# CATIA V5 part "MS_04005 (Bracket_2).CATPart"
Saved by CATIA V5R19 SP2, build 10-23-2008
Part number: MS_04005
Bounding box of the stored display mesh (mm): x -11.248 to 11.248, y 76.359 to 104.129, z 0 to 1.5
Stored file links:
  C:\Users\33645\Documents\02-Etudes\2019-ECL\Trans Semestres\01-EPSA\03-Trans Saisons\Git\ELIZ-2021\MS_Miscellaneous_Finish_Assembly\MS_A0400 (Firewall)\Chappes\FR_04004.2 (Chape 2).CATPart
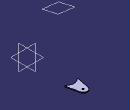
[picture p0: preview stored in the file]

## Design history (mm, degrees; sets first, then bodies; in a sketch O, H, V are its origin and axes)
SheetMetalParameters1: Thickness 1.5, BendRadius 4, KFactor 0.43175 {= log(min(100,max(20*SheetMetalParameters1.BendRadius,SheetMetalParameters1.Thickness)/SheetMetalParameters1.Thickness))/log(100)/2}, ReliefRadialLength 1, ReliefAxialLength 2, MinimumBendRadius 0
Body1 (main body)
  Sketch1 on xy-plane, origin (0, 0, 0), H (1, 0, 0), V (0, 1, 0)
    point P1 (-11.6743, 74.8566)
    line L1 (-11.2483, 76.9505) -> (-6.8595, 98.5247)
    point P2 (-6.8595, 98.5247)
    arc A1 centre (0, 97.1293) radius 7 from (-6.8595, 98.5247) to (0, 104.1293) cw
    point P4 (0, 104.1293)
    point P5 (0, 104.1293)
    point P6 (6.8595, 98.5247)
    point P7 (0, 97.1293)
    arc A2 centre (0, 97.1293) radius 7 from (6.8595, 98.5247) to (0, 104.1293) ccw
    point P8 (11.6743, 74.8566)
    line L2 (11.2483, 76.9505) -> (6.8595, 98.5247)
    circle A3 centre (0, 97.1293) radius 1.7
    arc A4 centre (0, 67.1293) radius 14 from (10.3874, 76.5156) to (-10.3874, 76.5156) ccw
    point P9 (0, 67.1293)
    arc A5 centre (10.7584, 76.8508) radius 0.5 from (10.3874, 76.5156) to (11.2483, 76.9505) ccw
    point P12 (10.7584, 76.8508)
    arc A6 centre (-10.7584, 76.8508) radius 0.5 from (-10.3874, 76.5156) to (-11.2483, 76.9505) cw
    point P15 (-10.7584, 76.8508)
    distance P7 A2 = 7
    radius A3 = 1.7
    radius A4 = 14
    distance P9 P7 = 30
    radius A5 = 0.5
    radius A6 = 0.5
    distance P12 P15 = 21.5167
    tangency: A1 L1, A2 A1, A5 L2, A5 A4, A6 L1, A6 A4
    symmetry: P4 P5 V, P2 P6 V, A1 A2 V, P1 P8 V, L1 L2 V
    fix: P9
    coincidence: A4 P8, L2 P8, A4 P1, L1 P1
  Wall1: Thickness 1.5, Profile Sketch1
  Plane1: stored without definition
  Line1 "Diag_SIS_Noeud_SIS-MH_Down_L": stored without definition
  Plane2: type Normal, Curve Line1
  Line2 "Diag_SIS_Noeud_SIS-MH_Down_L": stored without definition
  Line3 "Diag_SIS_Noeud_SIS-MH_Down_L": stored without definition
